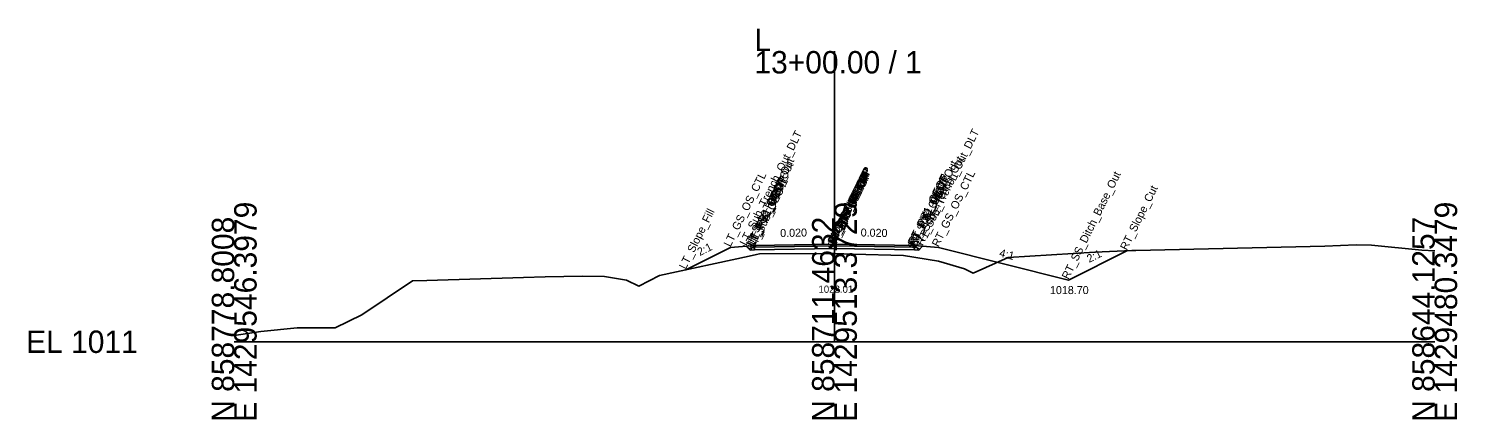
# Model space of a CAD drawing. Extents: x -26 to 153, y -10 to 13058.
# Drawn here: x -25.7 to 152.8, y 2990.3 to 3039.1 of the extents above; entities that cross this region are included whole.
import ezdxf

# ---------------------------------------------------------------- set-up
doc = ezdxf.new("R2010")
doc.units = 0
for name, color, linetype in [('Default', 7, 'Continuous'), ('Exist Cross Section Cell', 7, 'Continuous'), ('Exist XS Ground Line', 7, 'Continuous'), ('Prop CMT Pvmt Course 1', 7, 'Continuous'), ('Prop CMT Pvmt Course 2', 7, 'Continuous'), ('Prop CMT Pvmt Surface', 7, 'Continuous'), ('Prop CMT Pvmt Surface Shoulder', 7, 'Continuous'), ('Prop CMT Shld Paved Course 1', 7, 'Continuous'), ('Prop CMT Shld Paved Course 2', 7, 'Continuous'), ('Prop CMT Slope Grass', 7, 'Continuous'), ('Prop CMT Subgrade Daylight Point', 7, 'Continuous'), ('Prop CMT Subgrade Earthwork', 7, 'Continuous'), ('Prop XS Ditch Standard Text', 7, 'Continuous'), ('Prop XS Dump Level', 7, 'Continuous'), ('Prop XS SE Text', 7, 'Continuous'), ('Prop XS Side Slope Text', 7, 'Continuous')]:
    doc.layers.add(name, color=color, linetype=linetype)

msp = doc.modelspace()

# ---------------------------------------------------------------- linework, layer by layer
at = {"layer": 'Exist Cross Section Cell'}
for p, q in [((75, 3000), (75, 3036.29)), ((0, 3000), (75, 3000)), ((75, 3000), (150, 3000))]:
    msp.add_line(p, q, dxfattribs=at)
at = {"layer": 'Exist XS Ground Line'}
msp.add_lwpolyline([(0, 3000.79), (3.33, 3001.29), (7.86, 3001.73), (9.04, 3001.75), (12.6, 3001.73), (15.96, 3003.38), (22.29, 3007.62), (24.06, 3007.64), (36.14, 3008), (38.85, 3008.12), (43.5, 3008.2), (46.25, 3008.14), (49.01, 3007.67), (50.56, 3006.95), (53.14, 3008.26), (64.33, 3010.69), (65.28, 3010.9), (65.63, 3010.97), (74.66, 3011.02), (75, 3011.01), (77.34, 3010.94), (83.63, 3010.75), (87.99, 3010.07), (91.26, 3009.09), (92.35, 3008.57), (96.72, 3010.5), (107.55, 3011.17), (112.16, 3011.38), (112.65, 3011.38), (136.29, 3011.93), (140.2, 3012.1), (142.11, 3012.04), (148.38, 3011.42), (150, 3011.33)], dxfattribs=at)
at = {"layer": 'Prop CMT Pvmt Course 1'}
for points in [[(75, 3012.2), (65, 3012)], [(65, 3012), (65, 3011.79)], [(65, 3011.79), (75, 3011.99)], [(75, 3011.99), (75, 3012.2)], [(75, 3012.2), (85, 3012)], [(75, 3011.99), (75, 3012.2)], [(85, 3011.79), (75, 3011.99)], [(85, 3012), (85, 3011.79)]]:
    msp.add_lwpolyline(points, dxfattribs=at)
msp.add_lwpolyline([(75, 3011.99), (75, 3012.08), (75, 3012.08), (75, 3011.99)], close=True, dxfattribs=at)
msp.add_lwpolyline([(75, 3011.99), (75, 3012.08), (75, 3012.08), (75, 3011.99)], close=True, dxfattribs=at)
at = {"layer": 'Prop CMT Pvmt Course 2'}
for points in [[(75, 3011.99), (65, 3011.79)], [(75, 3011.66), (75, 3011.99)], [(75, 3011.66), (75, 3011.99)], [(75, 3011.99), (85, 3011.79)], [(65, 3011.79), (65, 3011.46)], [(65, 3011.46), (75, 3011.66)], [(85, 3011.46), (75, 3011.66)], [(85, 3011.79), (85, 3011.46)]]:
    msp.add_lwpolyline(points, dxfattribs=at)
at = {"layer": 'Prop CMT Pvmt Surface'}
for points in [[(75, 3012.2), (65, 3012)], [(75, 3012.2), (85, 3012)]]:
    msp.add_lwpolyline(points, dxfattribs=at)
at = {"layer": 'Prop CMT Pvmt Surface Shoulder'}
for points in [[(65, 3012), (65, 3012)], [(85, 3012), (85, 3012)]]:
    msp.add_lwpolyline(points, dxfattribs=at)
at = {"layer": 'Prop CMT Shld Paved Course 1'}
for points in [[(65, 3012), (64.79, 3011.79)], [(65, 3012), (65, 3012)], [(65, 3011.79), (65, 3012)], [(85, 3012), (85, 3012)], [(85, 3012), (85.21, 3011.79)], [(85, 3011.79), (85, 3012)], [(64.79, 3011.79), (65, 3011.79)], [(85.21, 3011.79), (85, 3011.79)]]:
    msp.add_lwpolyline(points, dxfattribs=at)
at = {"layer": 'Prop CMT Shld Paved Course 2'}
for points in [[(64.79, 3011.79), (64.45, 3011.45)], [(64.45, 3011.45), (65, 3011.46)], [(65, 3011.79), (64.79, 3011.79)], [(64.79, 3011.79), (64.79, 3011.79)], [(65, 3011.46), (65, 3011.79)], [(85, 3011.79), (85.21, 3011.79)], [(85, 3011.46), (85, 3011.79)], [(85.55, 3011.45), (85, 3011.46)], [(85.21, 3011.79), (85.21, 3011.79)], [(85.21, 3011.79), (85.55, 3011.45)]]:
    msp.add_lwpolyline(points, dxfattribs=at)
at = {"layer": 'Prop CMT Slope Grass'}
for points in [[(65, 3012), (62, 3011.76), (56.42, 3008.97)], [(85, 3012), (88, 3011.76), (104.24, 3007.7), (111.53, 3011.35)]]:
    msp.add_lwpolyline(points, dxfattribs=at)
at = {"layer": 'Prop CMT Subgrade Earthwork'}
for points in [[(64.45, 3011.45), (63.98, 3011.92)], [(85.55, 3011.45), (86.02, 3011.92)], [(65, 3011.46), (64.45, 3011.45)], [(75, 3011.66), (65, 3011.46)], [(75, 3011.66), (85, 3011.46)], [(85, 3011.46), (85.55, 3011.45)]]:
    msp.add_lwpolyline(points, dxfattribs=at)

# ---------------------------------------------------------------- texts
at = {"layer": 'Default'}
msp.add_text('-', height=0.0001, dxfattribs=at).set_placement((0, 3000))
at = {"layer": 'Exist Cross Section Cell'}
for s, p in [('L', (65, 3036.29)), ('13+00.00 / 1', (65, 3033.49)), ('EL 1011', (-26, 2998.6))]:
    msp.add_text(s, height=2.8, dxfattribs=at).set_placement(p)
for s, p in [('E 1429546.3979', (2.8, 2990)), ('E 1429513.3729', (77.8, 2990)), ('E 1429480.3479', (152.8, 2990)), ('N 858778.8008', (0, 2990)), ('N 858711.4632', (75, 2990)), ('N 858644.1257', (150, 2990))]:
    msp.add_text(s, height=2.8, rotation=90, dxfattribs=at).set_placement(p)
at = {"layer": 'Prop CMT Subgrade Daylight Point'}
msp.add_text('1022.01', height=0.9, dxfattribs=at).set_placement((73, 3006.11))
at = {"layer": 'Prop XS Ditch Standard Text'}
msp.add_text('1018.70', height=1, dxfattribs=at).set_placement((101.93, 3005.95))
at = {"layer": 'Prop XS Dump Level'}
for s, p in [('LT_Sub_Trench_Out_DLT', (63.98, 3011.92)), ('RT_Sub_Trench_Out_DLT', (86.02, 3011.92)), ('LT_Sub_Trench_Out', (64.45, 3011.45)), ('RT_PS2_Shelf_Out', (85.21, 3011.79)), ('RT_Sub_Trench_Out', (85.55, 3011.45)), ('LT_GS_OS_CTL', (62, 3011.76)), ('LT_PS2_Shelf_Out', (64.79, 3011.79)), ('LT_PV1_OEOT', (65, 3012)), ('RT_PV1_OEEOP', (75, 3012.08)), ('RT_PV2_OEEOP', (75, 3011.99)), ('LT_PV1_OEEOP', (75, 3012.08)), ('LT_PV2_OEEOP', (75, 3011.99)), ('RT_Sub_OEEOP', (75, 3011.66)), ('RT_PV1_IEEOP', (75, 3012.08)), ('RT_PV2_IEEOP', (75, 3011.99)), ('LT_Sub_OEEOP', (75, 3011.66)), ('LT_PV1_IEEOP', (75, 3012.08)), ('LT_PV2_IEEOP', (75, 3011.99)), ('RT_PV1_OEOT', (85, 3012)), ('RT_PS1_OEOP', (85, 3012)), ('RT_PV2_OEOT', (85, 3011.79)), ('RT_GS_OS_CTL', (88, 3011.76)), ('RT_SS_Ditch_Base_Out', (104.24, 3007.7)), ('LT_PS2_OEOP', (64.79, 3011.79)), ('LT_PS1_OEOP', (65, 3012)), ('LT_PV2_OEOT', (65, 3011.79)), ('LT_Sub_OEOT', (65, 3011.46)), ('RT_Sub_OEOT', (85, 3011.46)), ('RT_PS2_OEOP', (85.21, 3011.79)), ('RT_Slope_Cut', (111.53, 3011.35)), ('PV1_PGL', (75, 3012.2)), ('PV2_PGL', (75, 3011.99)), ('LT_Slope_Fill', (56.42, 3008.97))]:
    msp.add_text(s, height=1, rotation=63.5833, dxfattribs=at).set_placement(p)
at = {"layer": 'Prop XS SE Text'}
for rotation, p in [(1.1458, (68.23, 3013.07)), (358.8542, (78.27, 3013.14))]:
    msp.add_text('0.020', height=1, rotation=rotation, dxfattribs=at).set_placement(p)
at = {"layer": 'Prop XS Side Slope Text'}
for s, rotation, p in [('2:1', 26.5651, (58.17, 3010.68)), ('4:1', 345.9638, (95.53, 3010.65)), ('2:1', 26.5651, (106.84, 3009.84))]:
    msp.add_text(s, height=1, rotation=rotation, dxfattribs=at).set_placement(p)

doc.saveas('drawing.dxf')
